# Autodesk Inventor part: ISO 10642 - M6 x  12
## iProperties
Created: 2001-08
Part Number: ISO 10642 - M6 x  12
Catalog Web Link: file:///D:/Program%20Files/Autodesk/Inventor%205/Content/Iso/index.htm?doNavigateId=9774AB6A-0928-46EB-BF4B-FD24F3C420CC|12A166D6AA1D4CFABDA061F95C2D0FB|true
Description: Hexagon Socket Countersunk Head Screw
Document SubType Name: Standard Catalog Part
Standard: ISO 10642 - M6 x  12
Designer: Martin Budgell
Control State: 0
Master: False
Checked Out: False
Length Units: 11269
Angle Units: 11279
Time Units: 11290
Mass Units: 11283
Shininess: 3
Angle Display Precision: 2
Document Length Units: 11269
Document Angle Units: 11279
Document Time Units: 11290
Document Mass Units: 11283
Document Length Units Precision: 3
Document Angle Units Precision: 2
Compacted: True
CLASSIFICATION: 31161513 un/spsc
MANUFACTURER: ISO Standard System
Density: 0.0
Volumn: 0.0
Area: 0.0
PropertySet Name: Model Information
Author: Martin Budgell
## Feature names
1. Base1
